// Mitsubishi GX Works2 project: LM3200F_RS232C_sample_release   PLC: Q00UJ

PROGRAM MAIN
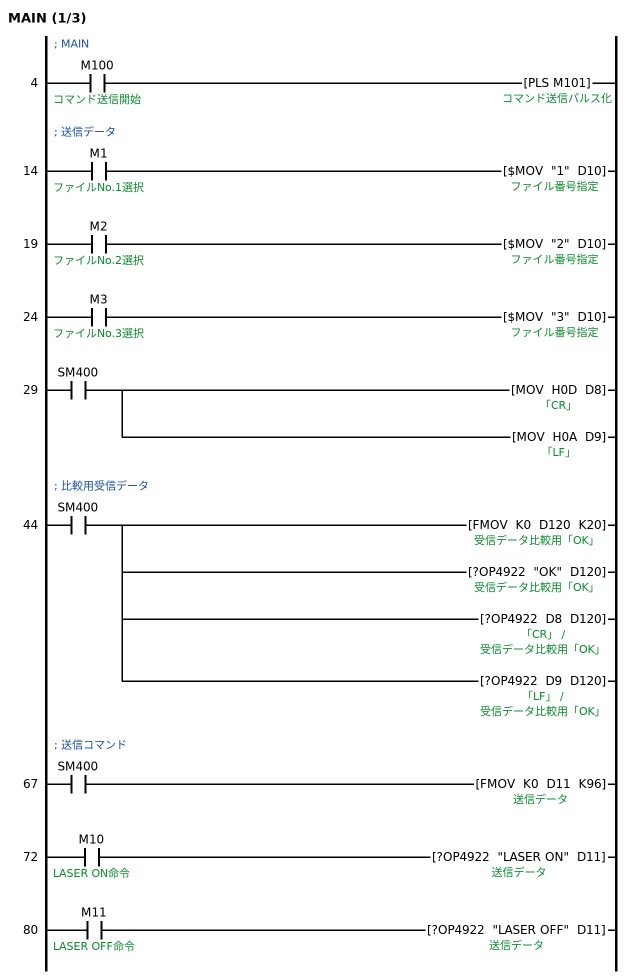
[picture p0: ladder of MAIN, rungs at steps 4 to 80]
; MAIN
4     LD      M100  ; コマンド送信開始
      PLS     M101  ; コマンド送信パルス化
; 送信データ
14    LD      M1  ; ファイルNo.1選択
      $MOV    "1" D10  ; ファイル番号指定
19    LD      M2  ; ファイルNo.2選択
      $MOV    "2" D10
24    LD      M3  ; ファイルNo.3選択
      $MOV    "3" D10
29    LD      SM400
      MOV     H0D D8  ; 「CR」
      MOV     H0A D9  ; 「LF」
; 比較用受信データ
44    LD      SM400
      FMOV    K0 D120 K20  ; 受信データ比較用「OK」
      ?OP4922 "OK" D120
      ?OP4922 D8 D120
      ?OP4922 D9 D120
; 送信コマンド
67    LD      SM400
      FMOV    K0 D11 K96  ; 送信データ
72    LD      M10  ; LASER ON命令
      ?OP4922 "LASER ON" D11
80    LD      M11  ; LASER OFF命令
      ?OP4922 "LASER OFF" D11
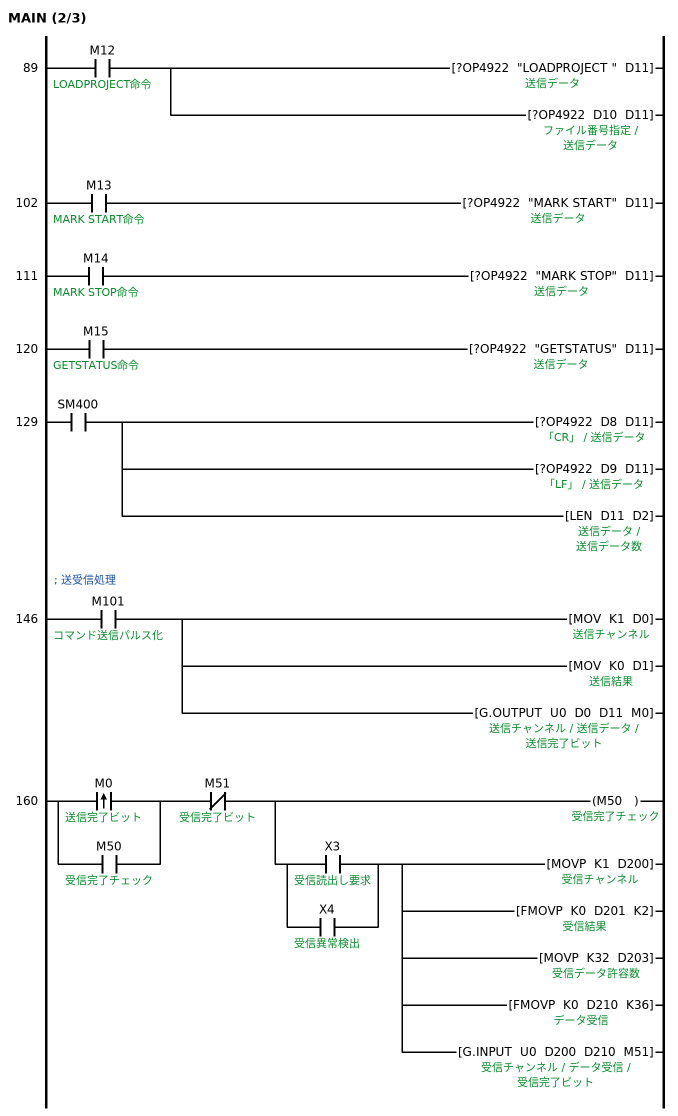
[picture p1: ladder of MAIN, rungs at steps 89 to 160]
89    LD      M12  ; LOADPROJECT命令
      ?OP4922 "LOADPROJECT " D11
      ?OP4922 D10 D11
102   LD      M13  ; MARK START命令
      ?OP4922 "MARK START" D11
111   LD      M14  ; MARK STOP命令
      ?OP4922 "MARK STOP" D11
120   LD      M15  ; GETSTATUS命令
      ?OP4922 "GETSTATUS" D11
129   LD      SM400
      ?OP4922 D8 D11
      ?OP4922 D9 D11
      LEN     D11 D2  ; 送信データ数
; 送受信処理
146   LD      M101  ; コマンド送信パルス化
      MOV     K1 D0  ; 送信チャンネル
      MOV     K0 D1  ; 送信結果
      G.OUTPUT U0 D0 D11 M0  ; 送信完了ビット
160   LDP     M0  ; 送信完了ビット
      OR      M50  ; 受信完了チェック
      ANI     M51  ; 受信完了ビット
      OUT     M50  ; 受信完了チェック
      LD      X3  ; 受信読出し要求
      OR      X4  ; 受信異常検出
      ANB
      MOVP    K1 D200  ; 受信チャンネル
      FMOVP   K0 D201 K2  ; 受信結果
      MOVP    K32 D203  ; 受信データ許容数
      FMOVP   K0 D210 K36  ; データ受信
      G.INPUT U0 D200 D210 M51
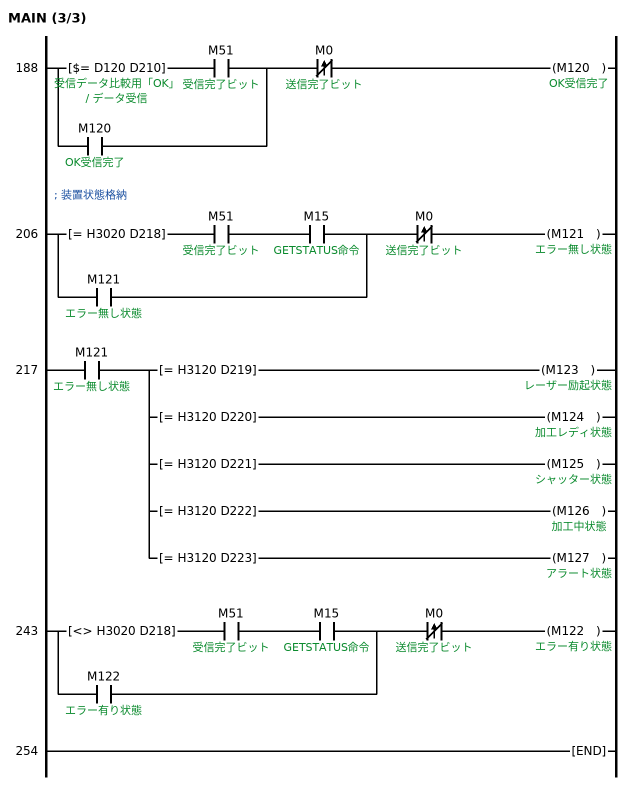
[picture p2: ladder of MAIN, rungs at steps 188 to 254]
188   LD$=    D120 D210  ; 受信データ比較用「OK」 / データ受信
      AND     M51  ; 受信完了ビット
      OR      M120  ; OK受信完了
      ANDPI   M0  ; 送信完了ビット
      OUT     M120  ; OK受信完了
; 装置状態格納
206   LD=     H3020 D218
      AND     M51  ; 受信完了ビット
      AND     M15  ; GETSTATUS命令
      OR      M121  ; エラー無し状態
      ANDPI   M0  ; 送信完了ビット
      OUT     M121  ; エラー無し状態
217   LD      M121  ; エラー無し状態
      MPS
      AND=    H3120 D219
      OUT     M123  ; レーザー励起状態
      MRD
      AND=    H3120 D220
      OUT     M124  ; 加工レディ状態
      MRD
      AND=    H3120 D221
      OUT     M125  ; シャッター状態
      MRD
      AND=    H3120 D222
      OUT     M126  ; 加工中状態
      MPP
      AND=    H3120 D223
      OUT     M127  ; アラート状態
243   LD<>    H3020 D218
      AND     M51  ; 受信完了ビット
      AND     M15  ; GETSTATUS命令
      OR      M122  ; エラー有り状態
      ANDPI   M0  ; 送信完了ビット
      OUT     M122  ; エラー有り状態
254   END
END_PROGRAM

// device comments not shown above
D202  ; 受信データ数
